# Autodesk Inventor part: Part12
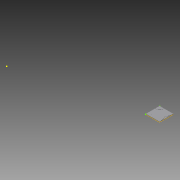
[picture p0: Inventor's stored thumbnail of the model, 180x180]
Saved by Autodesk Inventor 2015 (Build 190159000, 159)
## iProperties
Created: 2015-04
Part Number: Part12
Material: Generic
Document SubType Name: Modeling
Designer: TREINA5
Density: 1 g/cm^3
Appearance: Default
Mass: 128107 g
Surface Area: 49339.3 cm^2
Volume: 128107 cm^3
Author: TREINA5
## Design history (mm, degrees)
sketch "Sketch1"
  geometry: L1 (13480, 3000.034)-(13480, 2999.966); L2 (12499.868, 2999.966)-(13480, 2999.966); L3 (13480, 4245.02)-(13480, 3234.98); L4 (12000, 2999.966)-(12479.966, 2999.966); L5 (12499.868, 4479.966)-(13480, 4479.966); L6 (12000, 4479.966)-(12479.966, 4479.966); L7 (12000, 4000)-(12000, 4479.966); L8 (12000, 3499.835)-(12000, 3980.098); L9 (12000, 2999.966)-(12000, 3479.933); A1 r 1490.034 centre (11990, 2990.034) between (13480, 2999.966) and (13277.536, 3740); A2 r 1510 centre (11990, 2990.034) between (13480, 3234.98) and (13300.591, 3740); A3 r 490.068 centre (11990, 4489.966) between (12000, 4000) and (12479.967, 4480.001); A4 r 509.966 centre (11990, 4489.966) between (12000, 3980.098) and (12499.869, 4480.001); A5 r 490.068 centre (11990, 2989.966) between (12479.967, 2999.932) and (12000, 3479.933); A6 r 509.966 centre (11990, 2989.966) between (12499.869, 2999.932) and (12000, 3499.835); A7 r 1510 centre (11990, 4489.966) between (13300.591, 3740) and (13480, 4245.02); A8 r 1490.034 centre (11990, 4489.966) between (13277.537, 3740) and (13480, 4479.966); 10 further points
  constraints: 22 point on circle, 18 end point, 8 centre point
extrude "Extrusion1" new body sketch "Sketch1" distance "d0" = 60; taper "d1" = 0 deg
extrude "Extrusion2" new body sketch "Sketch1" distance "d2" = 60; taper "d3" = 0 deg
extrude "Extrusion3" new body sketch "Sketch1" distance "d4" = 60; taper "d5" = 0 deg
extrude "Extrusion4" new body sketch "Sketch1" distance "d6" = 60; taper "d7" = 0 deg
body "Solid1"
body "Solid2"
body "Solid3"
body "Solid4"
